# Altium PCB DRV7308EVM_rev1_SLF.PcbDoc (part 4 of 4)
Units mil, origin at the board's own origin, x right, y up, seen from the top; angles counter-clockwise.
Board outline 6187 x 6000 mil, 4 copper layers (Top Layer, Ground, Power, Bottom Layer), stack 61.2 mil thick; 306 components, 128 nets, 676 pads, 1026 vias.
Unrouted connection lines stored in the file: 208.
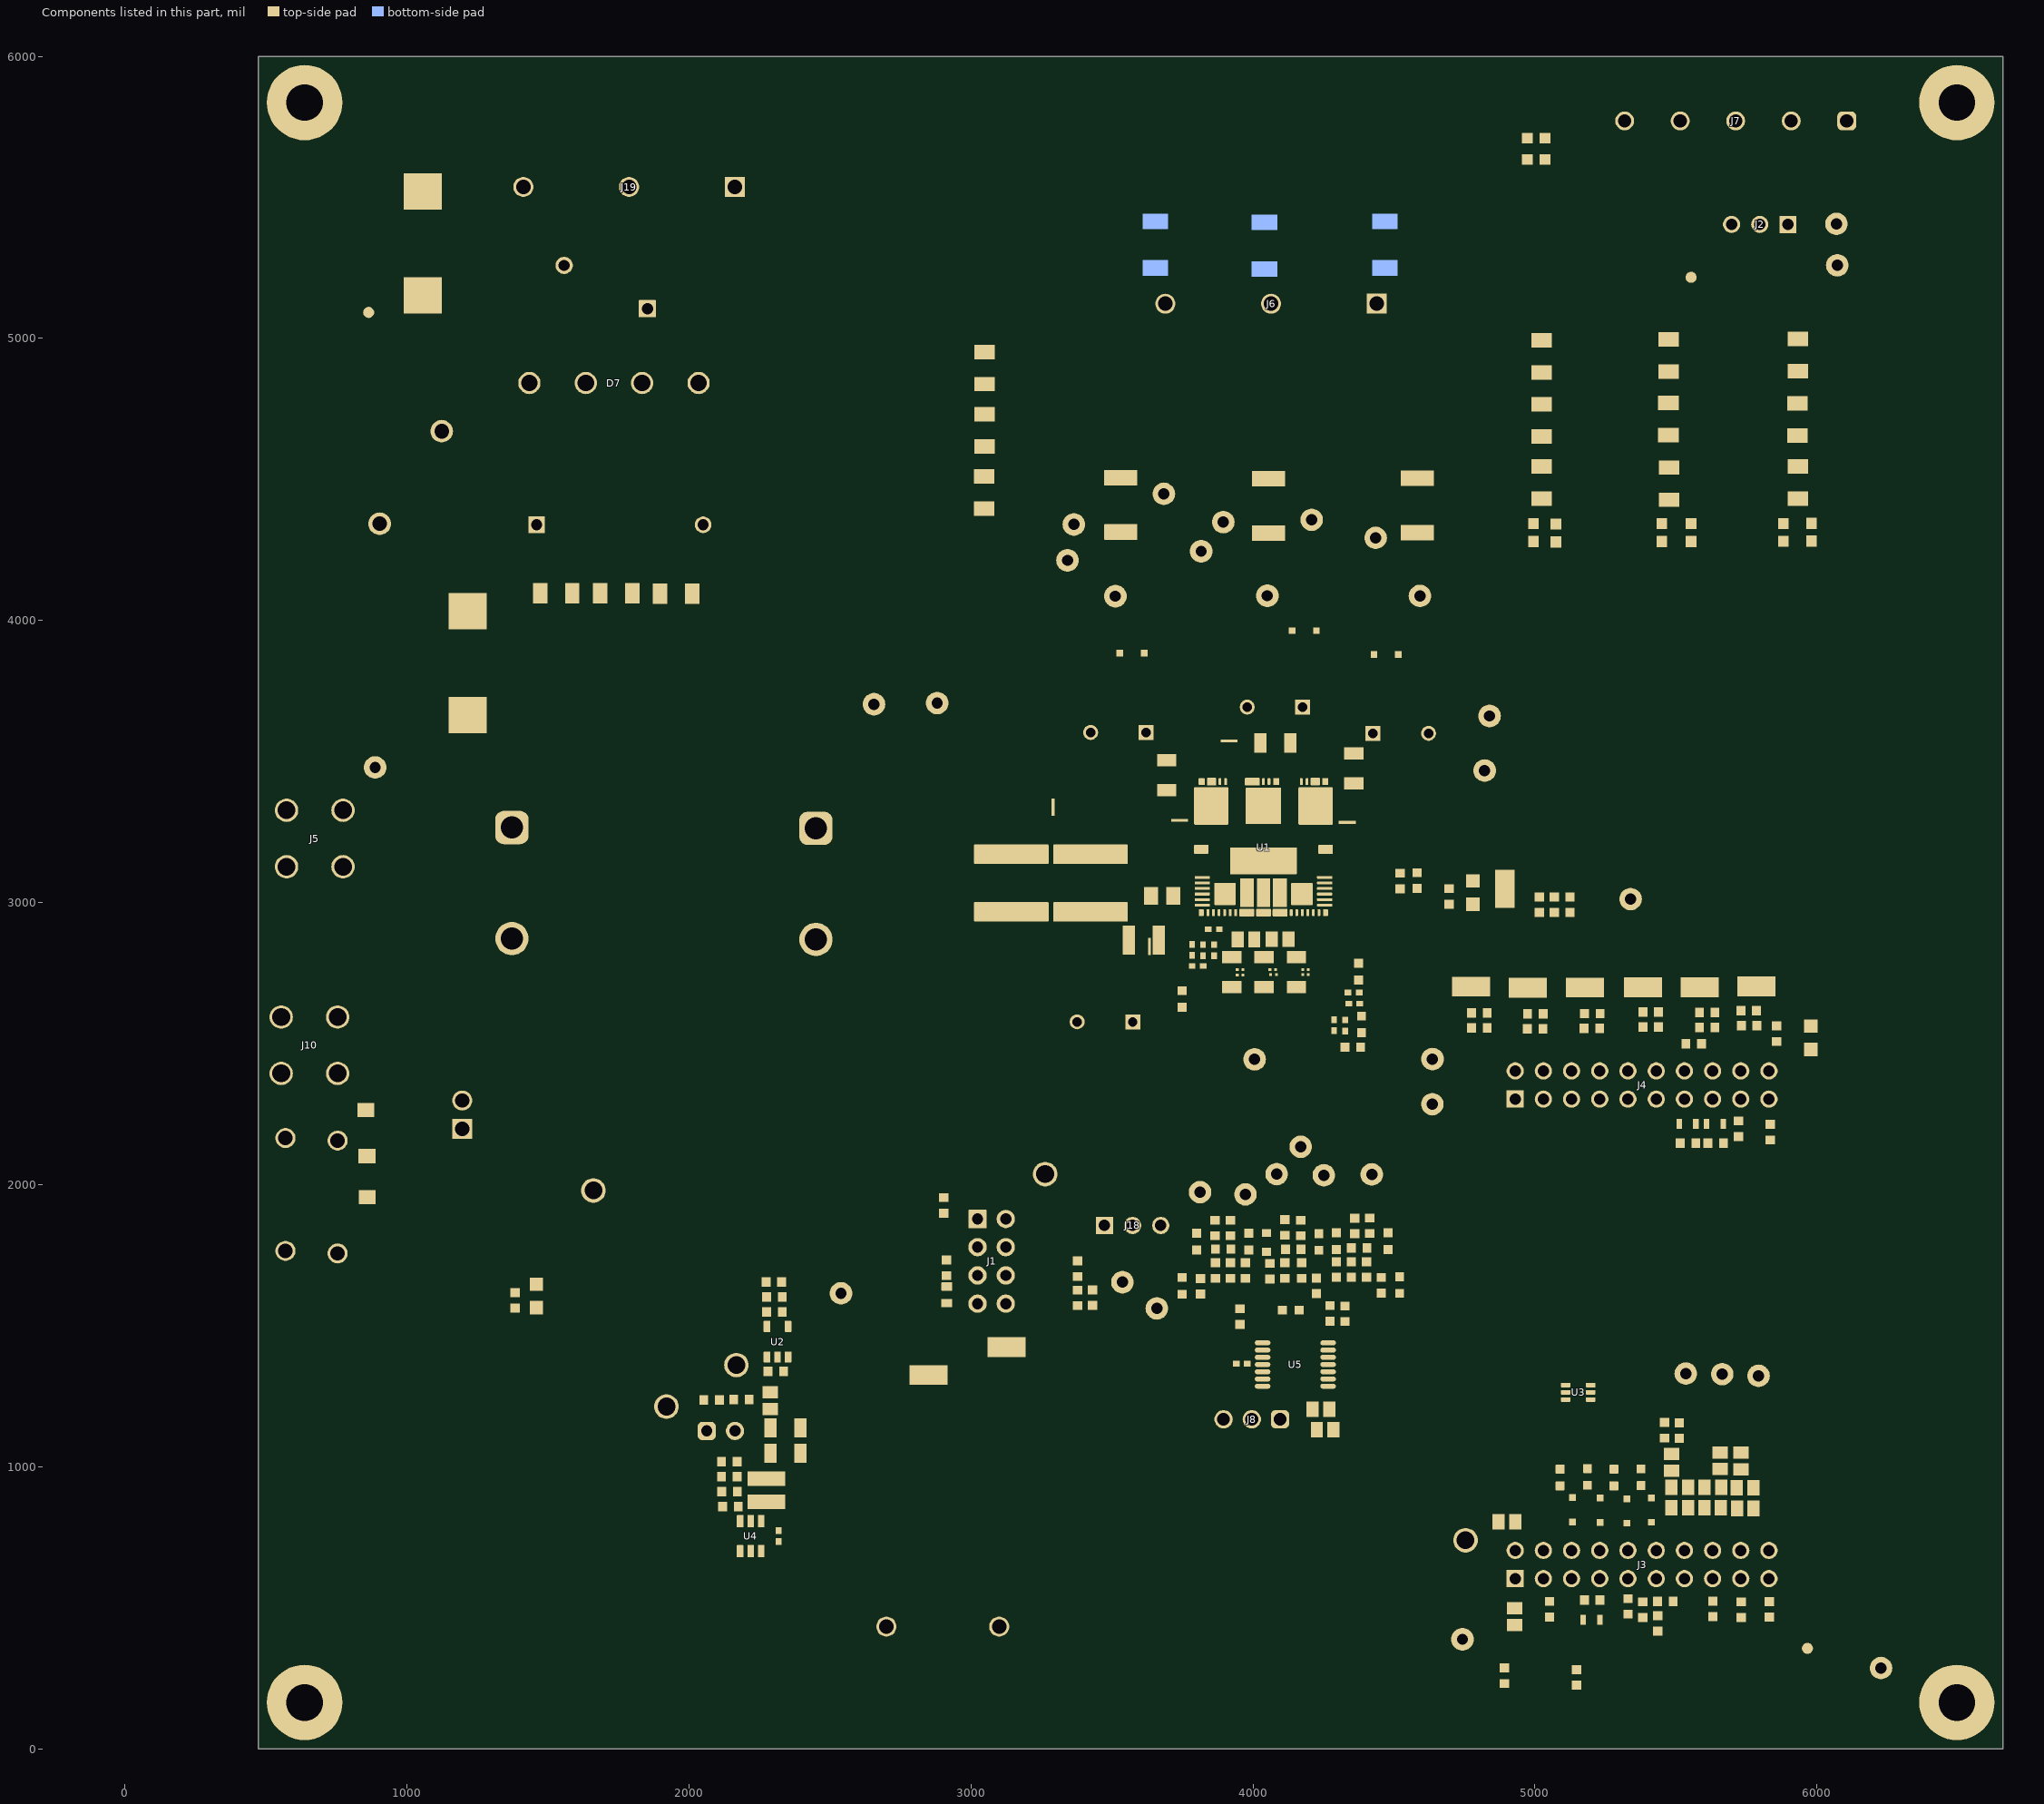
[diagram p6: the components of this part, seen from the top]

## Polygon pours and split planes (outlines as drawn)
VM on Top Layer "TOP_LAYER_VM_P328" (solid, remove dead copper, pour order 328): 1283,3731 1283,3531 1414,3400 1426.84,3400 1426.84,3373 862,3373 844,3391 844,3652 924,3732
NetF2_1 on Top Layer "TOP_LAYER_NETF2_1_P325" (solid, remove dead copper, pour order 325): 1284,3967 1284,4098 998,4384 876,4384 782,4290 782,3969 1280,3969 1282,3967
PGND on Top Layer "TOP_LAYER_PGND_P324" (solid, remove dead copper, pour order 324): 1143.57,2758.5 843,2457.93 843,2758.5
VM on Top Layer "TOP_LAYER_VM_P322" (solid, remove dead copper, pour order 322): 755,3414 532,3414 532,3108 557,3083 814,3083 931,3200 2950,3200 3012,3138 3557.15,3138 3591.15,3172 3838.7,3172 3838.7,3204.3 3838,3205 3490.15,3205 3295.15,3400 769,3400
NetD7_1 on Top Layer "TOP_LAYER_NETD7_1_P320" (solid, remove dead copper, pour order 320): 1472.18,4823.72 1472.18,4855.14 1472.18,4859.82 1422.28,4909.72 952.18,4909.72 889.18,4846.72 889.18,4562.72 1154.18,4562.72 1388.18,4796.72 1445.18,4796.72 1449.18,4800.72
GND on Top Layer "TOP_LAYER_GND_P317" (solid, remove dead copper, pour order 317): 5017,5810 6125,5810 6139,5796 6139,5676 6376,5439 6376,46 1000,46 1000,390 599,791 599,1644 857,1902 857,2558 1007,2558 1007,2348 1130,2225 1137,2232 2981,2232 3167,2046 3167,1952 3169,1950 3169,1853 4367,1853 4369,1855 4359,1865 4359,2819 4574,3034 6226,3034 6226,5251 5923,5554 5022,5554 5017,5559
NetF1_2 on Top Layer "TOP_LAYER_NETF1_2_P315" (solid, remove dead copper, pour order 315): 1454.03,5586.09 989.03,5586.09 977.03,5574.09 977.03,5452.09 983.03,5446.09 1453.03,5446.09 1454.03,5447.09
NetC56_2 on Top Layer "TOP_LAYER_NETC56_2_P314" (solid, remove dead copper, pour order 314): 1741.55,5576.11 1852.19,5576.11 1852.19,5462.48 1931,5383.67 1931,5037.56 1874.55,4981.11 1874.55,4693.76 2082.99,4485.33 2082.99,4311.86 2070.24,4299.11 1971.55,4299.11 1971.55,4417.11 1794,4594.67 1794,5057.87 1816,5079.87 1816,5390.67 1781.55,5425.11 1742.55,5425.11
NetC56_1 on Top Layer "TOP_LAYER_NETC56_1_P313" (solid, remove dead copper, pour order 313): 1588.31,5315 1588.31,5132.97 1588.31,5051.96 1674.31,4965.97 1674.31,4490.31 1499.44,4315.44 1426.84,4315.44 1379,4363.28 1379,4562 1592.31,4775.31 1592.31,4936.97 1442.31,5086.97 987.31,5086.97 980.31,5093.97 980.31,5210.97 984.31,5214.97 1116.31,5214.97 1185.31,5283.97 1425.31,5283.97 1456.35,5315
PGND on Top Layer "TOP_LAYER_PGND_P311" (solid, remove dead copper, pour order 311): 1994,4887 2364,4887 2531,4720 2531,4037 2094,3600 1531,3600 1531,3803 2053,3803 2281,4031 2281,4691 2171,4801 1994,4801
PGND on Top Layer "TOP_LAYER_PGND_P295" (solid, remove dead copper, pour order 295): 3840,2722 3797,2679 3797,2501 3964,2501 3964,2401 4025,2401 4050,2426 4050,2501 4251,2501 4251,2722
VM on Top Layer "TOP_LAYER_VM_P293" (solid, remove dead copper, pour order 293): 4324,3204 4235.92,3204 4233.92,3202 4233.92,3175.08 4236,3173 4324,3173
GND on Top Layer "TOP_LAYER_GND_P291" (solid, remove dead copper, pour order 291): 5016,5556 5197,5556 5197,5757 5016,5757
GND on Top Layer "TOP_LAYER_GND_P272" (solid, remove dead copper, pour order 272): 4951,4162 6069,4162 6069,4300 4951,4300
PGND on Top Layer "TOP_LAYER_PGND_P166" (solid, remove dead copper, pour order 166): 500,1724 854,1724 854,2750 3171,2750 3308,2613 3308,2084 3309,2085 3319,2085 3623.5,2389.5 3623.5,2992.5 3663,2992.5 3663,3040.23 3666.77,3044 3851,3044 3851,2980 4223,2980 4223,3037.95 4223.03,3009 4670,3009 4670,3206 4423,3206 4423,3155.24 4361.76,3094 4199,3094 4155.18,3123 4155.18,3195 3918.96,3195 3918.96,3123.81 3875,3094 3851,3094 3650,3094 3557,3001 500,3001
BK_OUT on Top Layer "TOP_LAYER_BK_OUT_P148" (solid, remove dead copper, pour order 148): 2208,933.44 2341,933.44 2342,934.44 2342,1200.44 2287,1255.44 2200,1255.44 2200,1220.28 2199.72,1220 2221,1220 2221,1010.44 2208,983.44
3V3 on Top Layer "TOP_LAYER_3V3_P102" (solid, remove dead copper, pour order 102): 2312,1628 2312,1850 2314,1852 2315,1851 2434,1851 2434,1629 2433,1628
GVDD on Top Layer "TOP_LAYER_GVDD_P004" (solid, remove dead copper, pour order 4): 3846,3045 3847,3046 3684,3046 3628,2990 3628,2799 3539,2710 3539,2330 3437,2228 1132,2228 1016,2112 1016,1858 1147,1727 1759,1727 2106,2074 3391,2074 3616,2299 3616,2688 3701,2773 3701,2941 3700,2942 3780,3022 3846,3022
OUTA on Top Layer "TOP_LAYER_OUTA_P086" (solid, remove dead copper, pour order 86): 3907.6,3276 3913,3281.4 3913,3410 3818.85,3504.15 3672.85,3504.15 3604,3573 3604,3867 3631,3894 3631,4364 3391,4364 3311,4284 3311,3605.42 3640.42,3276
NetC28_1 on Top Layer "TOP_LAYER_NETC28_1_P060" (solid, remove dead copper, pour order 60): 2289,1479.44 2304,1494.44 2304,1665.44 2299,1670.44 2250,1670.44 2246,1666.44 2246,1507.44 2245,1506.44 2245,1496.44 2264,1477.44 2288.85,1477.44
VREF_IN on Top Layer "TOP_LAYER_VREF_IN_P044" (solid, remove dead copper, pour order 44): 2150.62,1409.44 2123,1381.82 2123,1338 2191.56,1269.44 2239,1269.44 2239,1268.44 2262,1245.44 2316,1245.44 2316,1343.3 2289,1370.3 2289,1409.44
NetC2_1 on Top Layer "TOP_LAYER_NETC2_1_P040" (solid, remove dead copper, pour order 40): 2231,817.44 2262,848.44 2339.43,848.44 2342,851.02 2342,901.44 2208,901.44 2208,785.44 2231,785.44
NetC7_1 on Top Layer "TOP_LAYER_NETC7_1_P038" (solid, remove dead copper, pour order 38): 2193,785.44 2171,785.44 2142,814.44 2142,1057.44 2122,1077.44 2122,1134.48 2147.04,1159.44 2180,1159.44 2207,1132.44 2207,994.44 2193,980.44
OUT_C on Top Layer "TOP_LAYER_OUT_C_P028" (solid, remove dead copper, pour order 28): 4521,4437 4644,4437 4644,5163 4537,5270 4385,5270 4385,4573
OUT_A on Top Layer "TOP_LAYER_OUT_A_P024" (solid, remove dead copper, pour order 24): 3567,4440 3459,4440 3459,4684 3490,4715 3490,5214 3552,5276 3742,5276 3742,4617.69 3566,4441.69
OUT_B on Top Layer "TOP_LAYER_OUT_B_P020" (solid, remove dead copper, pour order 20): 4172.69,4439 4173.69,4440 4172,4441.69 4172,5273.09 3950.09,5273.09 3938,5261 3938,4519 4018,4439
OUTB on Top Layer "TOP_LAYER_OUTB_P018" (solid, remove dead copper, pour order 18): 4099.57,3278 3974,3278 3974,3494 3770,3698 3770,4199 3944,4373 4270,4373 4270,3682 4042,3454 4042,3445.16 4098.26,3445.16
OUTC on Top Layer "TOP_LAYER_OUTC_P014" (solid, remove dead copper, pour order 14): 4159,3276 4159,3409 4161,3411 4162,3410 4182.78,3410 4182.78,3441.93 4256,3515.15 4314.15,3515.15 4408,3609 4408,4261.23 4524.77,4378 4627,4378 4708,4297 4708,3469 4515,3276
SLA on Top Layer "TOP_LAYER_SLA_P010" (solid, remove dead copper, pour order 10): 4003,3086 4003,2925 3972,2894 3972,2784 3884,2784 3884,2882 3919,2917 3954,2952 3954,3086
SLB on Top Layer "TOP_LAYER_SLB_P008" (solid, remove dead copper, pour order 8): 4060,3086 4061,3085 4061,2923 4080.86,2903.14 4080.86,2782 3991.53,2782 3991.53,2902.53 4012,2923 4012,3086
SLC on Top Layer "TOP_LAYER_SLC_P006" (solid, remove dead copper, pour order 6): 4120,2944.87 4193,2871.87 4193,2783 4100.54,2783 4100.54,2893.46 4071,2923 4071,3086 4120,3086
NetF2_1 on Bottom Layer "BOTTOM_LAYER_NETF2_1_P326" (solid, remove dead copper, pour order 326): 1284,3967 1284,4098 998,4384 876,4384 782,4290 782,3969 1280,3969 1282,3967
NetD7_1 on Bottom Layer "BOTTOM_LAYER_NETD7_1_P321" (solid, remove dead copper, pour order 321): 1472.18,4823.72 1472.18,4855.14 1472.18,4859.82 1422.28,4909.72 952.18,4909.72 889.18,4846.72 889.18,4562.72 1154.18,4562.72 1388.18,4796.72 1445.18,4796.72 1449.18,4800.72
GND on Bottom Layer "BOTTOM_LAYER_GND_P316" (solid, remove dead copper, pour order 316): 5016,5811 5017,5810 5017,5563 6072,5563 6228,5407 6228,3035.8 6227,3034.8 6226.8,3035 6076,3035 6076,4302 4958,4302 4958,4169 5609,4169 5609,3262 5430,3083 4824,3083 4824,1891 4643,1710 4642.42,1710.58 3321.42,1710.58 3174,1858 3174,2636 3070,2740 855,2740 855,451.18 1261.18,45 6375,45 6375,5440 6137,5678 6137,5788 6131,5794 6131,5805 6127,5809 6105.44,5809
NetF1_2 on Bottom Layer "BOTTOM_LAYER_NETF1_2_P307" (solid, remove dead copper, pour order 307): 1452,5588 987,5588 975,5576 975,5454 981,5448 1451,5448 1452,5449
NetC56_2 on Bottom Layer "BOTTOM_LAYER_NETC56_2_P308" (solid, remove dead copper, pour order 308): 1742,5576 1852.64,5576 1852.64,5462.36 1931,5384 1931,5037 1875,4981 1875,4693.65 2083.44,4485.22 2083.44,4311.75 2070.69,4299 1972,4299 1972,4417 1794,4595 1794,4959.5 1794,5057.31 1817,5080.31 1817,5390 1782,5425 1743,5425
NetC56_1 on Bottom Layer "BOTTOM_LAYER_NETC56_1_P306" (solid, remove dead copper, pour order 306): 1587,5315 1587,5133 1587,5052 1673,4966 1673,4495.59 1492.88,4315.47 1425.53,4315.47 1380,4361 1380,4562.28 1591,4773.28 1591,4937 1441,5087 986,5087 979,5094 979,5211 983,5215 1115,5215 1184,5284 1424,5284 1455,5315
PGND on Bottom Layer "BOTTOM_LAYER_PGND_P310" (solid, remove dead copper, pour order 310): 1994,4887 2365,4887 2531,4721 2531,4039 1854,3362 1531,3362 1531,3803 1944,3803 2280,4139 2280,4692 2171,4801 1994,4801
OUT_C on Bottom Layer "BOTTOM_LAYER_OUT_C_P305" (solid, remove dead copper, pour order 305): 4381.4,5277 4555,5277 4555,5203 4553,5201 4381.4,5201
OUT_A on Bottom Layer "BOTTOM_LAYER_OUT_A_P304" (solid, remove dead copper, pour order 304): 3572.4,5278 3746,5278 3746,5204 3744,5202 3572.4,5202
OUT_B on Bottom Layer "BOTTOM_LAYER_OUT_B_P303" (solid, remove dead copper, pour order 303): 3950.4,5277 4124,5277 4124,5203 4122,5201 3950.4,5201
PGND on Bottom Layer "BOTTOM_LAYER_PGND_P266" (solid, remove dead copper, pour order 266): 3148,2775 3308,2615 3308,1837 4665,1837 4665,3206 3308,3206 3308,3004 1751,3004 1751,3255 2535,4039 2535,4554 3248,5267 3368,5387 4444,5387 4521,5387 4521,5435 2942,5435 2280,4773 2280,4131 1532,3383 1532,3004 503,3004 503,2127 820,2127 820,2775
OUTC on Bottom Layer "BOTTOM_LAYER_OUTC_P078" (solid, remove dead copper, pour order 78): 4706,4176 4619,4263 4457,4263 4410,4216 4410,3569 4357,3516 4256.12,3516 4183,3442.88 4183,3410.19 4160,3410.19 4160,3274 4512,3274 4706,3468
OUTB on Bottom Layer "BOTTOM_LAYER_OUTB_P076" (solid, remove dead copper, pour order 76): 4099.85,3278 3970.19,3278 3970.19,3489.81 3796,3664 3796,4217 3950,4371 4277,4371 4277,3660 4099.85,3482.85
OUTA on Bottom Layer "BOTTOM_LAYER_OUTA_P016" (solid, remove dead copper, pour order 16): 3913,3276 3913,3410 3893.48,3410.09 3893.48,3440.39 3825.86,3508 3666.43,3508 3603,3571.43 3603,3866 3631,3894 3631,4364 3391,4364 3311,4284 3311,3582 3606,3287 3795,3287 3795,3276
3V3 on Power "POWER_3V3_P100" (solid, remove dead copper, pour order 100): 2312,1628 2356,1628 2420,1564 2420,1495 3505,1495 4893,107 6086,1300 6086,2771 4453.5,1138.5 4264,1328 4264,1786 5086,2608 5086,3130 4607,3130 4607,2917 4311,2621 4311,2201 4016,1906 3668,1906 3614,1852 2312,1852

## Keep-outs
Keep-Out Layer:
  text ".Layer_Name" at 860.77,-1220.79 h35

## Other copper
Top Layer:
  rectangle net PGND: 4477,3174 4510,3203.7
  rectangle net VM: 4293.29,3173 4324,3204
  pour cut-out: 1020,3001 903,2884 500,2884 500,3001
  pour cut-out: 2208,901.44 2349,901.44 2349,933.44 2208,933.44
  text ".Layer_Name" at 860.77,-1220.79 h60
Bottom Layer:
  text ".Layer_Name" at 860.77,-1220.79 h60

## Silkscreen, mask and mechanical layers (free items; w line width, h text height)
Top Overlay:
  lines w10: 2384,5616 2372,5628 2372,5629 2372,5633 ; 2432,5633 2414,5633 2372,5633 ; 2581.22,5508.39 ccw(c2546,5506.68) 2581.26,5506.71 ; 2753.22,5507.71 ccw(c2718,5506) 2753.26,5506.03 ; 2930.96,5506.68 ccw(c2895.74,5504.97) 2931,5505 ; 2372,5633 2384,5645 2372,5633 ; 2436,5379 3001,5379 3001,5755.36 2998.64,5753 2436,5753 2436,5379
  text "5A ABS MAX" at 3901,5756 h50
  text "5A ABS MAX" at 913,5664 h50
  text "OUT_A" at 3579,5610 h50
  text "OUT_B" at 3976,5608 h50
  text "OUT_C" at 4396,5606.02 h50
  text "PE" at 2792.75,5590.43 h72.83
  text "+" at 2463.51,5579.43 h100
  text "-" at 2638.51,5573.43 h100
  text "PWR" at 5273,5492 h50
  text "HALLA" at 5450,5492 h50
  text "HALLB" at 5661,5492 h50
  text "HALLC" at 5864,5492 h50
  text "GND" at 6081,5492 h50
  text "EXT_PWR" at 6157,5380 h50
  text "EXT" at 5999,5361 h50 r90
  text "3.3V" at 5614,5358 h50 r90
  text "+" at 1334.43,5283.97 h50
  text "BRAKE" at 4987,2489 h35
  text "GND" at 4893.61,2487.19 h35
  text "HALLB" at 5616,2482 h35
  text "PGND" at 963,2284 h35
  text "GVDD" at 961.31,2177.02 h35
  text "INHA" at 4944.82,2013 h35 r90
  text "INLA" at 5044.82,2013 h35 r90
  text "INHB" at 5147.97,2012 h35 r90
  text "INLB" at 5246.82,2010 h35 r90
  text "INHC" at 5346.82,2007 h35 r90
  text "INLC" at 5446.82,2007 h35 r90
  text "HALLC" at 5542.82,1981 h35 r90
  text "5V/ns" at 3186,1881 h50
  text "10V/ns" at 3188,1759 h50
  text "GVDD" at 3449,1753 h50
  text "3.3V" at 3619,1752 h50
  text "20V/ns" at 3183,1654 h50
  text "40V/ns" at 3185,1558 h50
  text "GND" at 3824.45,1124.5 h50 r90
  text "ISENC" at 5748.11,1085.77 h35 r90
  text "ISENB" at 5647.11,1084.77 h35 r90
  text "VSENA" at 5147.82,1084 h35 r90
  text "VSENC" at 5332.43,1084 h35 r90
  text "VSENVM" at 5420.66,1084 h35 r90
  text "ISENA" at 5565.82,1084 h35 r90
  text "VSENB" at 5244.82,1083 h35 r90
  text "R73/R74" at 4184.82,1061 h50 r90
  text "3.3V" at 4930.7,320.69 h35 r90
  text "HALLC" at 5242.53,282.59 h35 r90
  text "nFAULT" at 5630.82,267.8 h35 r90
  text "ENABLE" at 5340.7,256.69 h35 r90
  text "VTEMP_IN" at 5060.84,231 h35 r90
  text ".Layer_Name" at 860.77,-1220.79 h35
Bottom Overlay:
  text ".Layer_Name" at 860.77,-1220.79 h35
Top Paste:
  text ".Layer_Name" at 860.77,-1220.79 h35
Bottom Paste:
  text ".Layer_Name" at 860.77,-1220.79 h35
Top Solder:
  text ".Layer_Name" at 860.77,-1220.79 h35
  text ".Layer_Name" at 860.77,-1220.79 h35
Bottom Solder:
  text ".Layer_Name" at 860.77,-1220.79 h35
Drill Guide:
  text ".Layer_Name" at 860.77,-1220.79 h35
M1 Board Outline:
  lines w10: 0,0 0,5223 ; 3253.32,-784.8 3253.77,-784.34 ; 473,0 473,6000 ; 473,0 6660,0 6660,6000 473,6000 ; 473,0 473,6000
  text ".Layer_Name" at 860.77,-1220.79 h35
M2 Board Dimensions:
  rectangle: 283.77,-637.3 408.77,-512.3
  rectangle: 408.77,-762.3 783.77,-637.3
  lines w7: 283.77,-637.3 1283.77,-637.3 ; 408.77,-762.3 408.77,-512.3 ; 533.77,-762.3 533.77,-512.3 ; 783.77,-762.3 783.77,-512.3 ; 1033.77,-762.3 1033.77,-512.3 ; 283.77,-762.3 1283.77,-762.3 1283.77,-512.3 283.77,-512.3 283.77,-762.3
  text ".Layer_Name" at 860.77,-1220.79 h35
M3 3D STEP Top:
  text ".Layer_Name" at 860.77,-1220.79 h35
M4 3D STEP Bottom:
  text ".Layer_Name" at 860.77,-1220.79 h35
M5 Assembly Top:
  lines w10: -8.23,-1292.46 6591.77,-1292.46 ; -8.23,-1089.13 6593.77,-1089.13 ; -8.23,-885.8 -8.23,-1495.8 3996.77,-1495.8 6593.77,-1495.8 6593.77,-885.8 -7.73,-885.8 -7.73,-1495.8 1567.77,-1495.8 ; 2456.77,-1495.8 2456.77,-885.8 ; 3723.77,-1089.13 3723.77,-885.8 ; 4563.77,-1089.13 4563.77,-885.8 ; 5185.77,-1502.3 5185.77,-1299.46
  text "COMPONENTS MARKED 'DNP' SHOULD NOT BE POPULATED." at 1437.27,-680.8 h60
  text "ASSEMBLY VARIANT:" at 1436.77,-796.3 h60
  text ".VariantName" at 2472.77,-796.3 h60
  text "PCB VIEWED FROM TOP SIDE" at 55.27,-1017.96 h60
  text "BOARD #:" at 2531.77,-1017.96 h60
  text ".PRJ_Number" at 3077.27,-1017.96 h60
  text "REV:" at 3921.77,-1017.96 h60
  text ".PCB_Rev" at 4213.27,-1017.96 h60
  text "SVN REV:" at 4759.77,-1017.96 h60
  text ".VersionControl_RevNumber" at 5265.77,-1017.96 h60
  text "TID #:" at 2531.77,-1221.3 h60
  text ".TID" at 3077.27,-1221.3 h60
  text "PLOT NAME =" at 55.27,-1426.63 h60
  text ".plot_File_Name" at 860.77,-1426.63 h60
  text "GENERATED    :" at 2533.77,-1426.63 h60
  text ".Print_Date" at 3403.27,-1426.63 h60
  text ".Print_Time" at 4132.27,-1426.63 h60
  text "TEXAS INSTRUMENTS" at 5396.77,-1426.63 h60
M6 Assembly Bottom:
  lines w10: -8.73,-1089.63 6593.27,-1089.63 ; -6.73,-1292.96 6593.27,-1292.96 ; 1399.27,-1502.8 1399.27,-1299.96 ; 2021.27,-1089.63 2021.27,-886.3 ; 2861.27,-1089.63 2861.27,-886.3 ; 4128.27,-1496.3 4128.27,-886.3 ; 5017.27,-1496.3 6592.77,-1496.3 6592.77,-886.3 -8.73,-886.3 -8.73,-1496.3 2588.27,-1496.3 6593.27,-1496.3 6593.27,-886.3
  text "COMPONENTS MARKED 'DNP' SHOULD NOT BE POPULATED." at 6385.77,-680.3 h60
  text ".VariantName" at 5341.77,-796.3 h60
  text "ASSEMBLY VARIANT:" at 6380.77,-796.3 h60
  text ".VersionControl_RevNumber" at 1319.27,-1018.46 h60
  text "SVN REV:" at 1825.27,-1018.46 h60
  text ".PCB_Rev" at 2371.77,-1018.46 h60
  text "REV:" at 2663.27,-1018.46 h60
  text ".PRJ_Number" at 3507.77,-1018.46 h60
  text "BOARD #:" at 4053.27,-1018.46 h60
  text "PCB VIEWED FROM BOTTOM SIDE" at 6529.77,-1018.46 h60
  text ".TID" at 3507.77,-1221.8 h60
  text "TID #:" at 4053.27,-1221.8 h60
  text "TEXAS INSTRUMENTS" at 1188.27,-1427.13 h60
  text ".Print_Time" at 2452.77,-1427.13 h60
  text ".Print_Date" at 3181.77,-1427.13 h60
  text "GENERATED    :" at 4051.27,-1427.13 h60
  text ".plot_File_Name" at 5724.27,-1427.13 h60
  text "PLOT NAME =" at 6529.77,-1427.13 h60
M9 Title Sheet:
  drawing of 57 lines, arcs and shapes, not listed
  text "1" at 1023.61,7674.2 h70
  text "2" at 3519.27,7674.2 h70
  text "3" at 6008.61,7674.2 h70
  text "4" at 8515.28,7674.2 h70
  text "5" at 11014.27,7674.2 h70
  text "6" at 13519.27,7674.2 h70
  text "A" at -132.73,6531.2 h70
  text "A" at 14667.27,6531.2 h70
  text "B" at -132.73,4151.2 h70
  text "B" at 14667.27,4151.2 h70
  text "C" at -132.73,1776.2 h70
  text "C" at 14667.27,1776.2 h70
  text "PROJECT TITLE:" at 11627.27,-84.8 h45
  text ".PRJ_Title" at 11677.27,-218.12 h70
  text "DESIGNED FOR:" at 11627.27,-385.8 h45
  text ".PRJ_Customer" at 11677.27,-525.8 h70
  text "D" at -132.73,-593.8 h70
  text "D" at 14667.27,-593.8 h70
  text "FILE NAME:" at 11627.27,-685.8 h45
  text ".PCB_File_Name_No_Path" at 11677.27,-805.8 h70
  text "Texas Instruments (TI) and/or its licensors do not warrant the accuracy or completeness of this specification" at 6657.77,-967.63 h45
  text "ENGINEER:" at 11627.27,-975.8 h45
  text "LAYOUT BY:" at 13132.27,-975.8 h45
  text "or any information contained therein. TI and/or its licensors do not warrant that this design will meet" at 6612.78,-1080.3 h45
  text ".PRJ_Engineer" at 11677.27,-1130.79 h70
  text ".PCB_Layout" at 13182.77,-1130.79 h70
  text "the specifications, will be suitable for your application or fit for any particular purpose, or will operate in" at 6612.78,-1192.97 h45
  text ".Layer_Name" at 860.77,-1220.79 h60
  text "ALTIUM DESIGNER VERSION:" at 13132.27,-1285.8 h45
  text "an implementation. TI and/or its licensors do not warrant that the design is production worthy. You should" at 6612.78,-1305.63 h45
  text "completely validate and test your design implementation to confirm the system functionality for your application." at 6657.77,-1418.3 h45
  text ".print_Scale" at 11677.27,-1419.12 h70
  text ".Application_BuildNumber" at 13182.77,-1419.12 h70
  text "1" at 1023.61,-1625.8 h70
  text "2" at 3519.27,-1625.8 h70
  text "3" at 6008.61,-1625.8 h70
  text "4" at 8515.28,-1625.8 h70
  text "5" at 11014.27,-1625.8 h70
  text "6" at 13519.27,-1625.8 h70
M10 Fab Notes:
  drawing of 189 lines, arcs and shapes, not listed
  text "DESIGN INFORMATION" at 12665.79,5993.88 h60
  text "MIN. TRACK WIDTH:" at 12021.23,5861.75 h60
  text "8" at 13117.47,5861.75 h60
  text "MIL" at 13272.23,5861.75 h60
  text "MIN. CLEARANCE:" at 12021.23,5737.63 h60
  text "0.2" at 13057.47,5737.63 h60
  text "mm" at 13272.23,5737.63 h60
  text "MIN. VIA PAD SIZE:" at 12021.23,5613.5 h60
  text "24" at 13087.48,5613.5 h60
  text "MIL" at 13272.23,5613.5 h60
  text "0.05mm (2MIL)" at 12716.23,5483.6 h60
  text "MINIMUM ANNULAR RING" at 11692,5475.38 h60
  text "EXTERNAL" at 13424.23,5475.38 h60
  text "PER" at 11892,5365.25 h60
  text "IPC-D-275 CLASS 2 LEVEL C" at 12112,5365.25 h60
  text "MIL, HOLES" at 13600.23,5264.77 h60
  text "+/-" at 13207.77,5256.19 h60
  text "+/-" at 14061.77,5256.19 h60
  text "REGISTRATION TOLERANCES:" at 11692,5255.12 h60
  text "METAL" at 12891.77,5255.12 h60
  text "5" at 13467.97,5255.12 h60
  text "3" at 14300.97,5255.12 h60
  text "MIL" at 14417.23,5255.12 h60
  text "HOLE SIZE TOLERANCE (UNLESS OTHERWISE SPECIFIED):" at 11692,5156.81 h60
  text "+/-" at 14061.77,5153.93 h60
  text "3" at 14300.97,5152.87 h60
  text "MIL" at 14417.23,5152.87 h60
  text "MATERIAL:" at 11617.23,5015.22 h60
  text "FR-4 High Tg" at 12603.67,4886.7 h60
  text "X" at 12459.23,4878.71 h60
  text "FR-408" at 12038.23,4874.19 h60
  text "OTHER" at 13526.23,4874.19 h60
  text "62 MIL (1.6mm) +/-10%" at 12358.33,4731.16 h60
  text "X" at 12238.23,4728.71 h60
  text "THICKNESS:" at 11692,4722.94 h60
  text "OTHER" at 13643.23,4722.94 h60
  text "TOLERANCE:" at 11692,4584.63 h60
  text "X" at 12540.23,4584.63 h60
  text "ANSI IPC-6012 TYPE 3 CLASS 2" at 12718.25,4584.63 h60
  text "OTHER +/-" at 12718.23,4440.44 h60
  text "BOW & TWIST:" at 11692,4295.25 h60
  text "X" at 12540.23,4295.25 h60
  text "ANSI IPC-6012 TYPE 3 CLASS 2" at 12718.25,4295.25 h60
  text "OTHER +/-" at 12718.23,4148.55 h60
  text "DRILLING:" at 11617.23,4017.93 h60
  text "NC_DRILL FILES" at 13378.23,3912.74 h60
  text "REFERENCE:" at 11692,3908.81 h60
  text "X" at 12349.23,3908.71 h60
  text "AS SHOWN" at 12527.23,3908.81 h60
  text "X" at 13250.23,3908.81 h60
  text "OTHER" at 13676.23,3766.55 h60
  text "PTH COPPER THICKNESS:" at 11691.68,3763.03 h60
  text "X" at 12830.91,3763.03 h60
  text "20-30 um" at 12958.91,3763.03 h60
  text "BOARD FINISH:" at 11617.23,3615.43 h60
  text "SILKSCREEN:" at 11772.45,3505.3 h60
  text "X" at 12730.23,3505.3 h60
  text "TOP" at 12847.23,3505.3 h60
  text "X" at 13240.23,3505.3 h60
  text "BOTTOM" at 13358.23,3505.3 h60
  text "SILKSCREEN COLOR:" at 11772.45,3350.11 h60
  text "X" at 12729.23,3350.11 h60
  text "WHITE" at 12847.23,3350.11 h60
  text "OTHER" at 13358.23,3350.11 h60
  text "X" at 12860.23,3206.67 h60
  text "GREEN" at 12978.23,3206.67 h60
  text "OTHER" at 13596.23,3206.67 h60
  text "SOLDER RESIST COLOR:" at 11772.45,3199.8 h60
  text "X" at 12860.23,3052.41 h60
  text "MATTE" at 12978.23,3052.41 h60
  text "SEMI-GLOSS" at 13595.77,3051.78 h60
  text "IMMERSION GOLD (ENIG)" at 12678.23,2879.64 h60
  text "ENEPIG" at 14015.77,2872.42 h60
  text "SURFACE FINISH:" at 11617.23,2871.42 h60
  text "X" at 12500.23,2871.42 h60
  text "IMM. TIN/SILVER OR EQUIV" at 11946.77,2734.11 h60
  text "OTHER" at 13378.23,2730.17 h60
  text "ARRAY/PANEL:" at 11617.23,2574.79 h60
  text "CUT AND TRIM PER M1 BOARD OUTLINE" at 12678.23,2566.57 h60
  text "N.C. ROUTE" at 12678.23,2430.6 h60
  text "X" at 13366.23,2430.6 h60
  text "V. SCORE" at 13544.23,2430.6 h60
  text "CERTIFICATION:" at 11617.23,2301.48 h60
  text "MATERIALS AND WORKMANSHIP FOR ALL PCBS" at 12342.23,2301.48 h60
  text "TO MEET OR EXCEED THE REQUIREMENTS OF:" at 12342.23,2207.41 h60
  text "X" at 11979.74,2078.78 h60
  text "ANSI IPC-A-600F CLASS ->" at 12107.73,2078.78 h60
  text "X" at 13755.74,2078.78 h60
  text "2" at 13865.73,2078.78 h60
  text "1" at 13550.73,2077.29 h60
  text "3" at 14219.73,2077.29 h60
  text "X" at 12791.74,1931.1 h60
  text "RoHS" at 12919.73,1931.1 h60
  text "OTHER" at 13564.13,1931.1 h60
  text "PER ORDER" at 13961.19,1931.1 h60
  text "ALL BOARDS MUST MEET OR EXCEED UL94-V0 REQUIREMENTS." at 11644.77,1777.27 h60
  text "PCB MUST BEAR THE UL94V-0 UL REGISTERED MATERIAL ID NUMBER" at 11644.77,1661.21 h60
  text "ADDITIONAL REQUIREMENTS:" at 11617.23,1491.78 h60
  text "MICROSECTION:" at 11692,1384.66 h60
  text "YES" at 12597.73,1384.66 h60
  text "REQUIRED" at 13459.23,1240.32 h60
  text "BARE BOARD ELEC. TEST:" at 11692,1237.47 h60
  text "NONE" at 12997.73,1237.47 h60
  text "X" at 13341.23,1237.47 h60
  text "PER ORDER" at 14051.23,1237.47 h60
  text "XX MIL VIAS REQUIRE NON-CONDUCTIVE FILL AND PLANARIZE" at 11860.15,1032.52 h59
  text "XX MIL VIAS REQUIRE CONDUCTIVE FILL AND PLANARIZE" at 11868.15,928.55 h60
  text "OUTER XX MIL TRACES REQUIRE 50 OHM SINGLE-ENDED IMPEDANCE" at 11867.16,765.16 h58
  text "LAYER 2 & 3 (INNER LAYERS) XX MIL WIDE, XX MIL SPACE / TRACES REQUIRE 100 OHM DIFFERENTIAL IMPEDANCE" at 11859.16,529.45 h60
  text ".Layer_Name" at 860.77,-1220.79 h60
M11 Gerber Information:
  lines w10: -8.23,-1292.46 6591.77,-1292.46 ; -8.23,-1089.13 6593.77,-1089.13 ; -8.23,-885.8 -8.23,-1495.8 3996.77,-1495.8 6593.77,-1495.8 6593.77,-885.8 -7.73,-885.8 -7.73,-1495.8 1567.77,-1495.8 ; 2456.77,-1495.8 2456.77,-885.8 ; 3723.77,-1089.13 3723.77,-885.8 ; 4563.77,-1089.13 4563.77,-885.8 ; 5185.77,-1502.3 5185.77,-1299.46
  text "ALL ARTWORK VIEWED FROM TOP SIDE" at 55.27,-1017.96 h60
  text "BOARD #:" at 2531.77,-1017.96 h60
  text ".PRJ_Number" at 3077.27,-1017.96 h60
  text "REV:" at 3921.77,-1017.96 h60
  text ".PCB_Rev" at 4213.27,-1017.96 h60
  text "SVN REV:" at 4759.77,-1017.96 h60
  text ".VersionControl_RevNumber" at 5265.77,-1017.96 h60
  text "LAYER NAME =" at 55.27,-1220.79 h60
  text "TID #:" at 2531.77,-1221.3 h60
  text ".TID" at 3077.27,-1221.3 h60
  text "PLOT NAME =" at 55.27,-1426.63 h60
  text ".plot_File_Name" at 860.77,-1426.63 h60
  text "GENERATED    :" at 2533.77,-1426.63 h60
  text ".Print_Date" at 3403.27,-1426.63 h60
  text ".Print_Time" at 4132.27,-1426.63 h60
  text "TEXAS INSTRUMENTS" at 5396.77,-1426.63 h60
M12 Stackup:
  drawing of 295 lines, arcs and shapes, not listed
  text ".Layer_Name" at 860.77,-1220.79 h60
  text "Layer" at 15606.58,-1911 h60
  text "Name" at 16016.49,-1911 h60
  text "Material" at 16946.23,-1911 h60
  text "Thickness" at 17806,-1911 h60
  text "Constant" at 18455.84,-1911 h60
  text "Board Layer Stack" at 19025.7,-1911 h60
  text "Top Overlay" at 16016.49,-2031 h60
  text "Top Solder" at 16016.49,-2151 h60
  text "Solder Resist" at 16946.23,-2151 h60
  text "0.40mil" at 17806,-2151 h60
  text "3.5" at 18455.84,-2151 h60
  text "1" at 15606.58,-2271 h60
  text "Top Layer" at 16016.49,-2271 h60
  text "4.20mil" at 17806,-2271 h60
  text "Dielectric 1" at 16016.49,-2391 h60
  text "FR-4 High Tg" at 16946.23,-2391 h60
  text "8.00mil" at 17806,-2391 h60
  text "4.2" at 18455.84,-2391 h60
  text "2" at 15606.58,-2511 h60
  text "Ground" at 16016.49,-2511 h60
  text "1.40mil" at 17806,-2511 h60
  text "Dielectric 2" at 16016.49,-2631 h60
  text "FR-4 High Tg" at 16946.23,-2631 h60
  text "34.00mil" at 17806,-2631 h60
  text "4.2" at 18455.84,-2631 h60
  text "3" at 15606.58,-2751 h60
  text "Power" at 16016.49,-2751 h60
  text "1.40mil" at 17806,-2751 h60
  text "Dielectric 3" at 16016.49,-2871 h60
  text "FR-4 High Tg" at 16946.23,-2871 h60
  text "8.00mil" at 17806,-2871 h60
  text "4.2" at 18455.84,-2871 h60
  text "4" at 15606.58,-2991 h60
  text "Bottom Layer" at 16016.49,-2991 h60
  text "4.20mil" at 17806,-2991 h60
  text "Bottom Solder" at 16016.49,-3111 h60
  text "Solder Resist" at 16946.23,-3111 h60
  text "0.40mil" at 17806,-3111 h60
  text "3.5" at 18455.84,-3111 h60
  text "Bottom Overlay" at 16016.49,-3231 h60
M13 Component Bodies Top:
  text ".Layer_Name" at 860.77,-1220.79 h60
M14 Component Bodies Bottom:
  text ".Layer_Name" at 860.77,-1220.79 h60
M15 Courtyards Top:
  text ".Layer_Name" at 860.77,-1220.79 h60
M16 Courtyards Bottom:
  text ".Layer_Name" at 860.77,-1220.79 h60
Drill Drawing:
  circle w10: c5647.49,3109.96 r16.58
  circle w10: c5647.49,3109.96 r27.63
  circle w10: c5647.49,2985.64 r27.63
  lines w10: 5619.86,1770.07 5675.11,1770.07 5647.49,1714.81 5619.86,1770.07 ; 5619.86,1977.27 5633.67,1977.27 5633.67,1963.45 5661.3,1963.45 5661.3,1977.27 5675.11,1977.27 5675.11,2004.89 5661.3,2004.89 5661.3,2018.71 5633.67,2018.71 5633.67,2004.89 5619.86,2004.89 5619.86,1977.27 ; 5619.86,2087.77 5675.11,2087.77 5675.11,2143.03 5619.86,2143.03 5619.86,2087.77 ; 5619.86,2225.91 5633.67,2225.91 5633.67,2212.09 5661.3,2212.09 5661.3,2225.91 5675.11,2225.91 5675.11,2253.53 5661.3,2253.53 5661.3,2267.35 5633.67,2267.35 5633.67,2253.53 5619.86,2253.53 5619.86,2225.91 ; 5619.86,2336.41 5619.86,2350.23 5633.67,2364.04 5619.86,2377.85 5619.86,2391.67 5633.67,2391.67 5647.49,2377.85 5661.3,2391.67 5675.11,2391.67 5675.11,2377.85 5661.3,2364.04 5675.11,2350.23 5675.11,2336.41 5661.3,2336.41 5647.49,2350.23 5633.67,2336.41 5619.86,2336.41 ; 5619.86,2515.99 5675.11,2515.99 5647.49,2460.73 5619.86,2515.99 ; 5619.86,2585.05 5647.49,2598.87 5675.11,2585.05 5661.3,2612.68 5675.11,2640.31 5647.49,2626.49 5619.86,2640.31 5633.67,2612.68 5619.86,2585.05 ; 5619.86,2709.37 5647.49,2723.19 5675.11,2709.37 5661.3,2737 5675.11,2764.63 5647.49,2750.81 5619.86,2764.63 5633.67,2737 5619.86,2709.37 ; 5619.86,2847.51 5633.67,2847.51 5647.49,2833.69 5661.3,2847.51 5675.11,2847.51 5661.3,2861.32 5675.11,2875.13 5661.3,2875.13 5647.49,2888.95 5633.67,2875.13 5619.86,2875.13 5633.67,2861.32 5619.86,2847.51 ; 5619.86,3206.65 5675.11,3206.65 5675.11,3261.91 5619.86,3261.91 5619.86,3206.65 ; 5619.86,3482.92 5647.49,3455.29 5675.11,3482.92 5647.49,3510.55 5619.86,3482.92 ; 5630.91,1759.02 5664.06,1759.02 5647.49,1725.86 5630.91,1759.02 ; 5630.91,2098.82 5664.06,2098.82 5664.06,2131.98 5630.91,2131.98 5630.91,2098.82 ; 5630.91,2231.43 5639.2,2231.43 5639.2,2223.14 5655.77,2223.14 5655.77,2231.43 5664.06,2231.43 5664.06,2248.01 5655.77,2248.01 5655.77,2256.3 5639.2,2256.3 5639.2,2248.01 5630.91,2248.01 5630.91,2231.43 ; 5630.91,2720.42 5647.49,2728.71 5664.06,2720.42 5655.77,2737 5664.06,2753.58 5647.49,2745.29 5630.91,2753.58 5639.2,2737 5630.91,2720.42 ; 5630.91,2853.03 5639.2,2853.03 5647.49,2844.74 5655.77,2853.03 5664.06,2853.03 5655.77,2861.32 5664.06,2869.61 5655.77,2869.61 5647.49,2877.9 5639.2,2869.61 5630.91,2869.61 5639.2,2861.32 5630.91,2853.03
  lines w12: 5569.77,1553.2 8801.26,1553.2 ; 5569.77,3666.64 8801.26,3666.64 ; 5907.63,1428.88 5907.63,3790.96 ; 6239.63,1428.88 6239.63,3790.96 ; 6876.2,1428.88 6876.2,3790.96 ; 7135.34,1428.88 7135.34,3790.96 ; 7510.49,1428.88 7510.49,3790.96 ; 8234.82,1428.88 8234.82,3790.96 ; 5569.77,1428.88 8801.26,1428.88 8801.26,3790.96 5569.77,3790.96 5569.77,1428.88
  text "Symbol" at 5644.36,3703.93 h72
  text "Quantity" at 5944.93,3703.93 h72
  text "Finished Hole Size" at 6276.93,3703.93 h72
  text "Plated" at 6913.49,3703.93 h72
  text "Hole Type" at 7172.63,3703.93 h72
  text "Drill Layer Pair" at 7547.79,3703.93 h72
  text "Hole Tolerance" at 8272.12,3703.93 h72
  text "57" at 5944.93,3579.61 h60
  text "7.87mil (0.200mm)" at 6276.93,3579.61 h60
  text "PTH" at 6913.49,3579.61 h60
  text "Round" at 7172.63,3579.61 h60
  text "Top Layer - Bottom Layer" at 7547.79,3579.61 h60
  text "B" at 5619.08,3569.62 h55.25
  text "945" at 5944.93,3455.29 h60
  text "10.00mil (0.254mm)" at 6276.93,3455.29 h60
  text "PTH" at 6913.49,3455.29 h60
  text "Round" at 7172.63,3455.29 h60
  text "Top Layer - Bottom Layer" at 7547.79,3455.29 h60
  text "42" at 5944.93,3330.97 h60
  text "19.69mil (0.500mm)" at 6276.93,3330.97 h60
  text "PTH" at 6913.49,3330.97 h60
  text "Round" at 7172.63,3330.97 h60
  text "Top Layer - Bottom Layer" at 7547.79,3330.97 h60
  text "E" at 5619.08,3320.98 h55.25
  text "8" at 5944.93,3206.65 h60
  text "33.47mil (0.850mm)" at 6276.93,3206.65 h60
  text "PTH" at 6913.49,3206.65 h60
  text "Round" at 7172.63,3206.65 h60
  text "Top Layer - Bottom Layer" at 7547.79,3206.65 h60
  text "4" at 5944.93,3082.33 h60
  text "39.37mil (1.000mm)" at 6276.93,3082.33 h60
  text "PTH" at 6913.49,3082.33 h60
  text "Round" at 7172.63,3082.33 h60
  text "Top Layer - Bottom Layer" at 7547.79,3082.33 h60
  text "45" at 5944.93,2958.01 h60
  text "40.00mil (1.016mm)" at 6276.93,2958.01 h60
  text "PTH" at 6913.49,2958.01 h60
  text "Round" at 7172.63,2958.01 h60
  text "Top Layer - Bottom Layer" at 7547.79,2958.01 h60
  text "46" at 5944.93,2833.69 h60
  text "40.16mil (1.020mm)" at 6276.93,2833.69 h60
  text "PTH" at 6913.49,2833.69 h60
  text "Round" at 7172.63,2833.69 h60
  text "Top Layer - Bottom Layer" at 7547.79,2833.69 h60
  text "3" at 5944.93,2709.37 h60
  text "45.28mil (1.150mm)" at 6276.93,2709.37 h60
  text "PTH" at 6913.49,2709.37 h60
  text "Round" at 7172.63,2709.37 h60
  text "Top Layer - Bottom Layer" at 7547.79,2709.37 h60
  text "5" at 5944.93,2585.05 h60
  text "47.24mil (1.200mm)" at 6276.93,2585.05 h60
  text "PTH" at 6913.49,2585.05 h60
  text "Round" at 7172.63,2585.05 h60
  text "Top Layer - Bottom Layer" at 7547.79,2585.05 h60
  text "8" at 5944.93,2460.73 h60
  text "51.18mil (1.300mm)" at 6276.93,2460.73 h60
  text "PTH" at 6913.49,2460.73 h60
  text "Round" at 7172.63,2460.73 h60
  text "Top Layer - Bottom Layer" at 7547.79,2460.73 h60
  text "6" at 5944.93,2336.41 h60
  text "51.18mil (1.300mm)" at 6276.93,2336.41 h60
  text "PTH" at 6913.49,2336.41 h60
  text "Round" at 7172.63,2336.41 h60
  text "Top Layer - Bottom Layer" at 7547.79,2336.41 h60
  text "+/-3.94mil" at 8272.12,2336.41 h60
  text "2" at 5944.93,2212.09 h60
  text "52.00mil (1.321mm)" at 6276.93,2212.09 h60
  text "PTH" at 6913.49,2212.09 h60
  text "Round" at 7172.63,2212.09 h60
  text "Top Layer - Bottom Layer" at 7547.79,2212.09 h60
  text "4" at 5944.93,2087.77 h60
  text "59.06mil (1.500mm)" at 6276.93,2087.77 h60
  text "PTH" at 6913.49,2087.77 h60
  text "Round" at 7172.63,2087.77 h60
  text "Top Layer - Bottom Layer" at 7547.79,2087.77 h60
  text "8" at 5944.93,1963.45 h60
  text "62.99mil (1.600mm)" at 6276.93,1963.45 h60
  text "PTH" at 6913.49,1963.45 h60
  text "Round" at 7172.63,1963.45 h60
  text "Top Layer - Bottom Layer" at 7547.79,1963.45 h60
  text "+3.94mil/-0.00mil" at 8272.12,1963.45 h60
  text "5" at 5944.93,1839.13 h60
  text "63.00mil (1.600mm)" at 6276.93,1839.13 h60
  text "PTH" at 6913.49,1839.13 h60
  text "Round" at 7172.63,1839.13 h60
  text "Top Layer - Bottom Layer" at 7547.79,1839.13 h60
  text "F" at 5619.08,1829.14 h55.25
  text "4" at 5944.93,1714.81 h60
  text "78.74mil (2.000mm)" at 6276.93,1714.81 h60
  text "PTH" at 6913.49,1714.81 h60
  text "Round" at 7172.63,1714.81 h60
  text "Top Layer - Bottom Layer" at 7547.79,1714.81 h60
  text "+/-3.94mil" at 8272.12,1714.81 h60
  text "7" at 5944.93,1590.49 h60
  text "129.92mil (3.300mm)" at 6276.93,1590.49 h60
  text "PTH" at 6913.49,1590.49 h60
  text "Round" at 7172.63,1590.49 h60
  text "Top Layer - Bottom Layer" at 7547.79,1590.49 h60
  text "D" at 5619.08,1580.5 h55.25
  text "1199 Total" at 5944.93,1466.17 h60
  text ".Layer_Name" at 860.77,-1220.79 h60
Mechanical 17:
  text ".Layer_Name" at 860.77,-1220.79 h60
Mechanical 18:
  text ".Layer_Name" at 860.77,-1220.79 h60
Mechanical 19:
  text ".Layer_Name" at 860.77,-1220.79 h60

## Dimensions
283.77,-762.3 to 1283.77,-762.3 on M2 Board Dimensions
283.77,-362.3 to 473,6000 on M2 Board Dimensions
283.77,-362.3 to 6660,0 on M2 Board Dimensions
